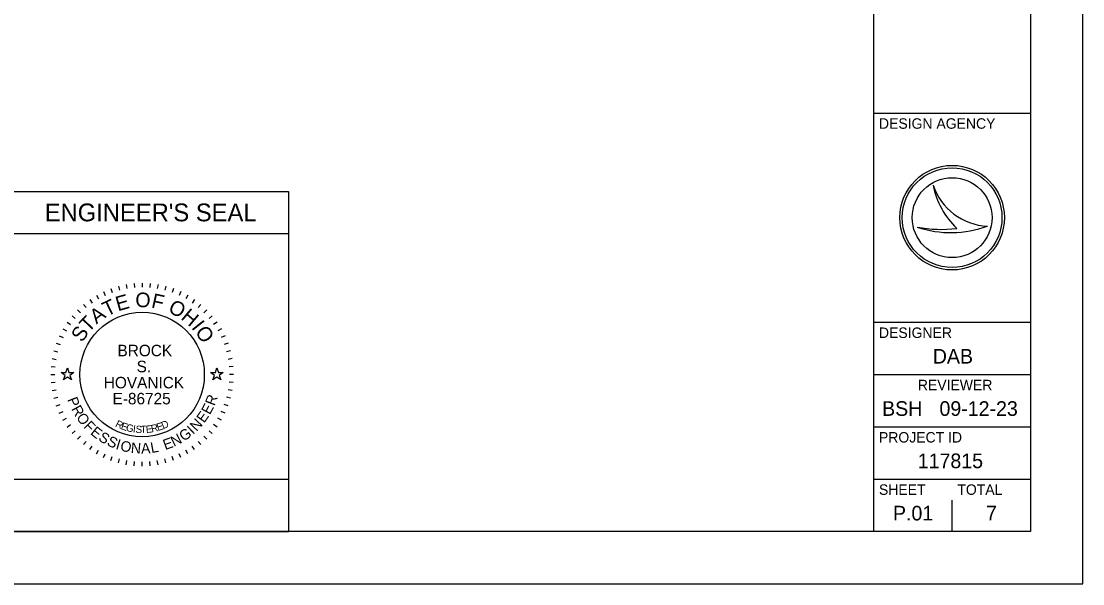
# Model space of a CAD drawing. Extents: x -19.9 to 41.9, y 0 to 32.3.
# Drawn here: x 23.84 to 34, y 0 to 5.38 of the extents above; entities that cross this region are included whole.
import ezdxf

# ---------------------------------------------------------------- set-up
doc = ezdxf.new("R2010")
doc.units = 0
for name, color, linetype in [('Default', 7, 'Continuous'), ('SH_Border', 7, 'Continuous'), ('SH_Cut_Line', 7, 'Continuous'), ('SH_Data', 7, 'Continuous')]:
    doc.layers.add(name, color=color, linetype=linetype)

msp = doc.modelspace()

# ---------------------------------------------------------------- linework, layer by layer
at = {"layer": 'Default'}
for p, q in [((24.774, 2.845), (24.784, 2.807)), ((24.848, 2.862), (24.855, 2.822)), ((24.924, 2.872), (24.927, 2.832)), ((25, 2.875), (25, 2.835)), ((25.076, 2.872), (25.073, 2.832)), ((25.152, 2.862), (25.145, 2.822)), ((25.226, 2.845), (25.216, 2.807)), ((24.563, 2.758), (24.583, 2.723)), ((24.63, 2.793), (24.647, 2.757)), ((24.701, 2.822), (24.714, 2.785)), ((25.299, 2.822), (25.286, 2.785)), ((25.37, 2.793), (25.353, 2.757)), ((25.437, 2.758), (25.417, 2.723)), ((24.438, 2.67), (24.463, 2.64)), ((24.498, 2.717), (24.521, 2.684)), ((25.502, 2.717), (25.479, 2.684)), ((25.562, 2.67), (25.537, 2.64)), ((24.33, 2.562), (24.36, 2.537)), ((24.381, 2.619), (24.41, 2.59)), ((25.619, 2.619), (25.59, 2.59)), ((25.67, 2.562), (25.64, 2.537)), ((24.283, 2.502), (24.316, 2.479)), ((25.717, 2.502), (25.684, 2.479)), ((24.207, 2.37), (24.243, 2.353)), ((24.242, 2.438), (24.277, 2.418)), ((25.758, 2.438), (25.723, 2.418)), ((25.793, 2.37), (25.757, 2.353)), ((24.178, 2.299), (24.215, 2.286)), ((25.822, 2.299), (25.785, 2.286)), ((24.138, 2.152), (24.178, 2.145)), ((24.155, 2.226), (24.193, 2.216)), ((25.845, 2.226), (25.807, 2.216)), ((25.862, 2.152), (25.822, 2.145)), ((24.128, 2.076), (24.168, 2.073)), ((25.872, 2.076), (25.832, 2.073)), ((24.125, 2), (24.165, 2)), ((25.875, 2), (25.835, 2)), ((24.128, 1.924), (24.168, 1.927)), ((24.138, 1.848), (24.178, 1.855)), ((25.862, 1.848), (25.822, 1.855)), ((25.872, 1.924), (25.832, 1.927)), ((24.155, 1.774), (24.193, 1.784)), ((25.845, 1.774), (25.807, 1.784)), ((24.178, 1.701), (24.215, 1.714)), ((24.207, 1.63), (24.243, 1.647)), ((25.793, 1.63), (25.757, 1.647)), ((25.822, 1.701), (25.785, 1.714)), ((24.242, 1.563), (24.277, 1.583)), ((25.758, 1.563), (25.723, 1.583)), ((24.283, 1.498), (24.316, 1.521)), ((24.33, 1.438), (24.36, 1.463)), ((25.67, 1.438), (25.64, 1.463)), ((25.717, 1.498), (25.684, 1.521)), ((24.381, 1.381), (24.41, 1.41)), ((24.438, 1.33), (24.463, 1.36)), ((25.562, 1.33), (25.537, 1.36)), ((25.619, 1.381), (25.59, 1.41)), ((24.498, 1.283), (24.521, 1.316)), ((24.563, 1.242), (24.583, 1.277)), ((24.63, 1.207), (24.647, 1.243)), ((25.37, 1.207), (25.353, 1.243)), ((25.437, 1.242), (25.417, 1.277)), ((25.502, 1.283), (25.479, 1.316)), ((24.701, 1.178), (24.714, 1.215)), ((24.774, 1.155), (24.784, 1.193)), ((24.848, 1.138), (24.855, 1.178)), ((24.924, 1.128), (24.927, 1.168)), ((25, 1.125), (25, 1.165)), ((25.076, 1.128), (25.073, 1.168)), ((25.152, 1.138), (25.145, 1.178)), ((25.226, 1.155), (25.216, 1.193)), ((25.299, 1.178), (25.286, 1.215))]:
    msp.add_line(p, q, dxfattribs=at)
for points in [[(24.224, 2.02), (24.271, 2.02), (24.285, 2.065), (24.299, 2.02), (24.346, 2.02), (24.308, 1.992), (24.323, 1.948), (24.285, 1.975), (24.247, 1.948), (24.262, 1.992)], [(25.654, 2.02), (25.701, 2.02), (25.715, 2.065), (25.729, 2.02), (25.776, 2.02), (25.738, 1.992), (25.753, 1.948), (25.715, 1.975), (25.677, 1.948), (25.692, 1.992)]]:
    msp.add_lwpolyline(points, close=True, dxfattribs=at)
msp.add_circle((25, 2), 0.595, dxfattribs=at)
at = {"layer": 'SH_Border'}
for p, q in [((32, 0.5), (32, 21.5)), ((32, 4.5), (33.5, 4.5)), ((32, 2.5), (33.5, 2.5)), ((32, 2), (33.5, 2)), ((32, 1.5), (33.5, 1.5)), ((32, 1), (33.5, 1))]:
    msp.add_line(p, q, dxfattribs=at)
msp.add_lwpolyline([(1.5, 21.5), (33.5, 21.5), (33.5, 0.5), (1.5, 0.5)], close=True, dxfattribs=at)
at = {"layer": 'SH_Cut_Line'}
msp.add_lwpolyline([(0, 0), (34, 0), (34, 22), (0, 22)], close=True, dxfattribs=at)
at = {"layer": 'SH_Data'}
for p, q in [((32.567, 3.81), (32.567, 3.81)), ((23.6, 3.75), (26.4, 3.75)), ((26.4, 3.75), (26.4, 0.5)), ((32.75, 3.5), (32.75, 3.5)), ((32.417, 3.41), (32.417, 3.41)), ((33.087, 3.419), (33.087, 3.419)), ((23.6, 3.35), (26.4, 3.35)), ((32.75, 0.5), (32.75, 0.8)), ((32.375, 0.675), (32.375, 0.675)), ((23.6, 0.5), (26.4, 0.5))]:
    msp.add_line(p, q, dxfattribs=at)
msp.add_lwpolyline([(23.6, 0.5), (23.6, 1), (26.4, 1), (26.4, 0.5)], close=True, dxfattribs=at)
for radius in [0.5, 0.477, 0.477, 0.382]:
    msp.add_circle((32.75, 3.5), radius, dxfattribs=at)
for centre, radius, start, end in [((33.116, 3.998), 0.58, 198.9257, 198.9319), ((33.347, 3.97), 0.796, 191.6379, 191.6421), ((33.116, 3.998), 0.58, 198.9319, 267.1657), ((33.347, 3.97), 0.796, 191.6421, 226.0947), ((32.739, 4.37), 1.013, 251.4576, 290.0832), ((32.648, 4.654), 1.266, 259.4964, 259.4995), ((32.739, 4.37), 1.013, 251.4527, 251.4576), ((32.648, 4.654), 1.266, 259.4995, 276.6672)]:
    msp.add_arc(centre, radius, start, end, dxfattribs=at)

# ---------------------------------------------------------------- texts
at = {"layer": 'Default'}
for s, height, rotation, p in [('E', 0.14, 15.7571, (24.768, 2.604)), ('O', 0.14, 359.7812, (24.935, 2.644)), ('F', 0.14, 347.4362, (25.081, 2.642)), ('T', 0.14, 25.7167, (24.662, 2.552)), ('O', 0.14, 332.2586, (25.24, 2.602)), ('T', 0.14, 46.4344, (24.488, 2.396)), ('A', 0.14, 36.4747, (24.563, 2.478)), ('H', 0.14, 319.9136, (25.363, 2.536)), ('S', 0.14, 57.1924, (24.428, 2.301)), ('I', 0.14, 308.367, (25.466, 2.448)), ('O', 0.14, 303.1491, (25.502, 2.409)), ('P', 0.1, 291.494, (24.282, 1.762)), ('E', 0.1, 61.9951, (25.648, 1.61)), ('R', 0.1, 69.2322, (25.692, 1.695)), ('R', 0.1, 298.7311, (24.319, 1.672)), ('O', 0.1, 306.4666, (24.365, 1.588)), ('E', 0.1, 54.758, (25.593, 1.531)), ('F', 0.1, 314.7068, (24.434, 1.498)), ('R', 0.07, 334.487, (24.737, 1.505)), ('E', 0.07, 341.04, (24.791, 1.48)), ('G', 0.07, 347.4752, (24.841, 1.462)), ('R', 0.07, 11.9184, (25.092, 1.447)), ('E', 0.07, 17.6836, (25.15, 1.46)), ('D', 0.07, 23.3052, (25.201, 1.477)), ('N', 0.1, 47.0224, (25.52, 1.451)), ('E', 0.1, 321.4393, (24.498, 1.435)), ('S', 0.1, 328.6764, (24.574, 1.375)), ('I', 0.07, 353.7858, (24.909, 1.447)), ('S', 0.07, 356.8926, (24.936, 1.443)), ('T', 0.07, 3.0061, (24.986, 1.439)), ('E', 0.07, 6.0117, (25.039, 1.441)), ('N', 0.1, 27.3113, (25.304, 1.308)), ('G', 0.1, 35.0469, (25.398, 1.357)), ('I', 0.1, 43.287, (25.487, 1.421)), ('S', 0.1, 335.9134, (24.656, 1.327)), ('I', 0.1, 343.1505, (24.741, 1.29)), ('O', 0.1, 346.8859, (24.784, 1.275)), ('N', 0.1, 355.1261, (24.889, 1.252)), ('A', 0.1, 2.8617, (24.992, 1.244)), ('L', 0.1, 10.0987, (25.089, 1.249)), ('E', 0.1, 20.0742, (25.221, 1.277))]:
    msp.add_text(s, height=height, rotation=rotation, dxfattribs=at).set_placement(p)
for s, p in [('BROCK', (24.764, 2.175)), ('S.', (24.947, 2.022)), ('HOVANICK', (24.633, 1.868)), ('E-86725', (24.717, 1.715))]:
    msp.add_text(s, height=0.11, dxfattribs=at).set_placement(p)
at = {"layer": 'SH_Data'}
for s, height, p in [('DESIGN AGENCY', 0.1, (32.05, 4.35)), ("ENGINEER'S SEAL", 0.17, (24.068, 3.465)), ('DESIGNER', 0.1, (32.05, 2.35)), ('DAB', 0.14, (32.565, 2.105)), ('REVIEWER', 0.1, (32.422, 1.85)), ('BSH', 0.14, (32.08, 1.605)), ('09-12-23', 0.14, (32.629, 1.605)), ('PROJECT ID', 0.1, (32.05, 1.35)), ('117815', 0.14, (32.421, 1.105)), ('SHEET', 0.1, (32.05, 0.85)), ('TOTAL', 0.1, (32.8, 0.85)), ('P.01', 0.14, (32.184, 0.605)), ('7', 0.14, (33.074, 0.605))]:
    msp.add_text(s, height=height, dxfattribs=at).set_placement(p)

doc.saveas('drawing.dxf')
